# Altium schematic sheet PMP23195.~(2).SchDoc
size 431 x 279 mm; Date: Not shown in title block; ApprovedBy: Not shown in title block; CheckedBy: Not shown in title block; Author: Not shown in title block; CompanyName: Not shown in title block; Engineer: Not shown in title block; Organization: Not shown in title block; Address1: Not shown in title block; Address2: Not shown in title block; Address3: Not shown in title block; Address4: Not shown in title block; DocumentNumber: 1; Revision: Use project parameter SCH_Rev; SheetNumber: 1; SheetTotal: 2; PageSetup: Record=PageOptions¦CenterHorizontal=True¦CenterVertical=True¦PrintScale=1.00¦XCorrection=1.00¦YCorrection=1.00¦PrintKind=0¦BorderSize=5000000¦LeftOffset=0¦BottomOffset=0¦Orientation=2¦PaperLength=1000¦PaperWidth=1000¦Scale=100¦PaperSource=15¦PrintQuality=600¦MediaType=1¦DitherType=10¦PaperKind=Letter¦PrintScaleMode=1
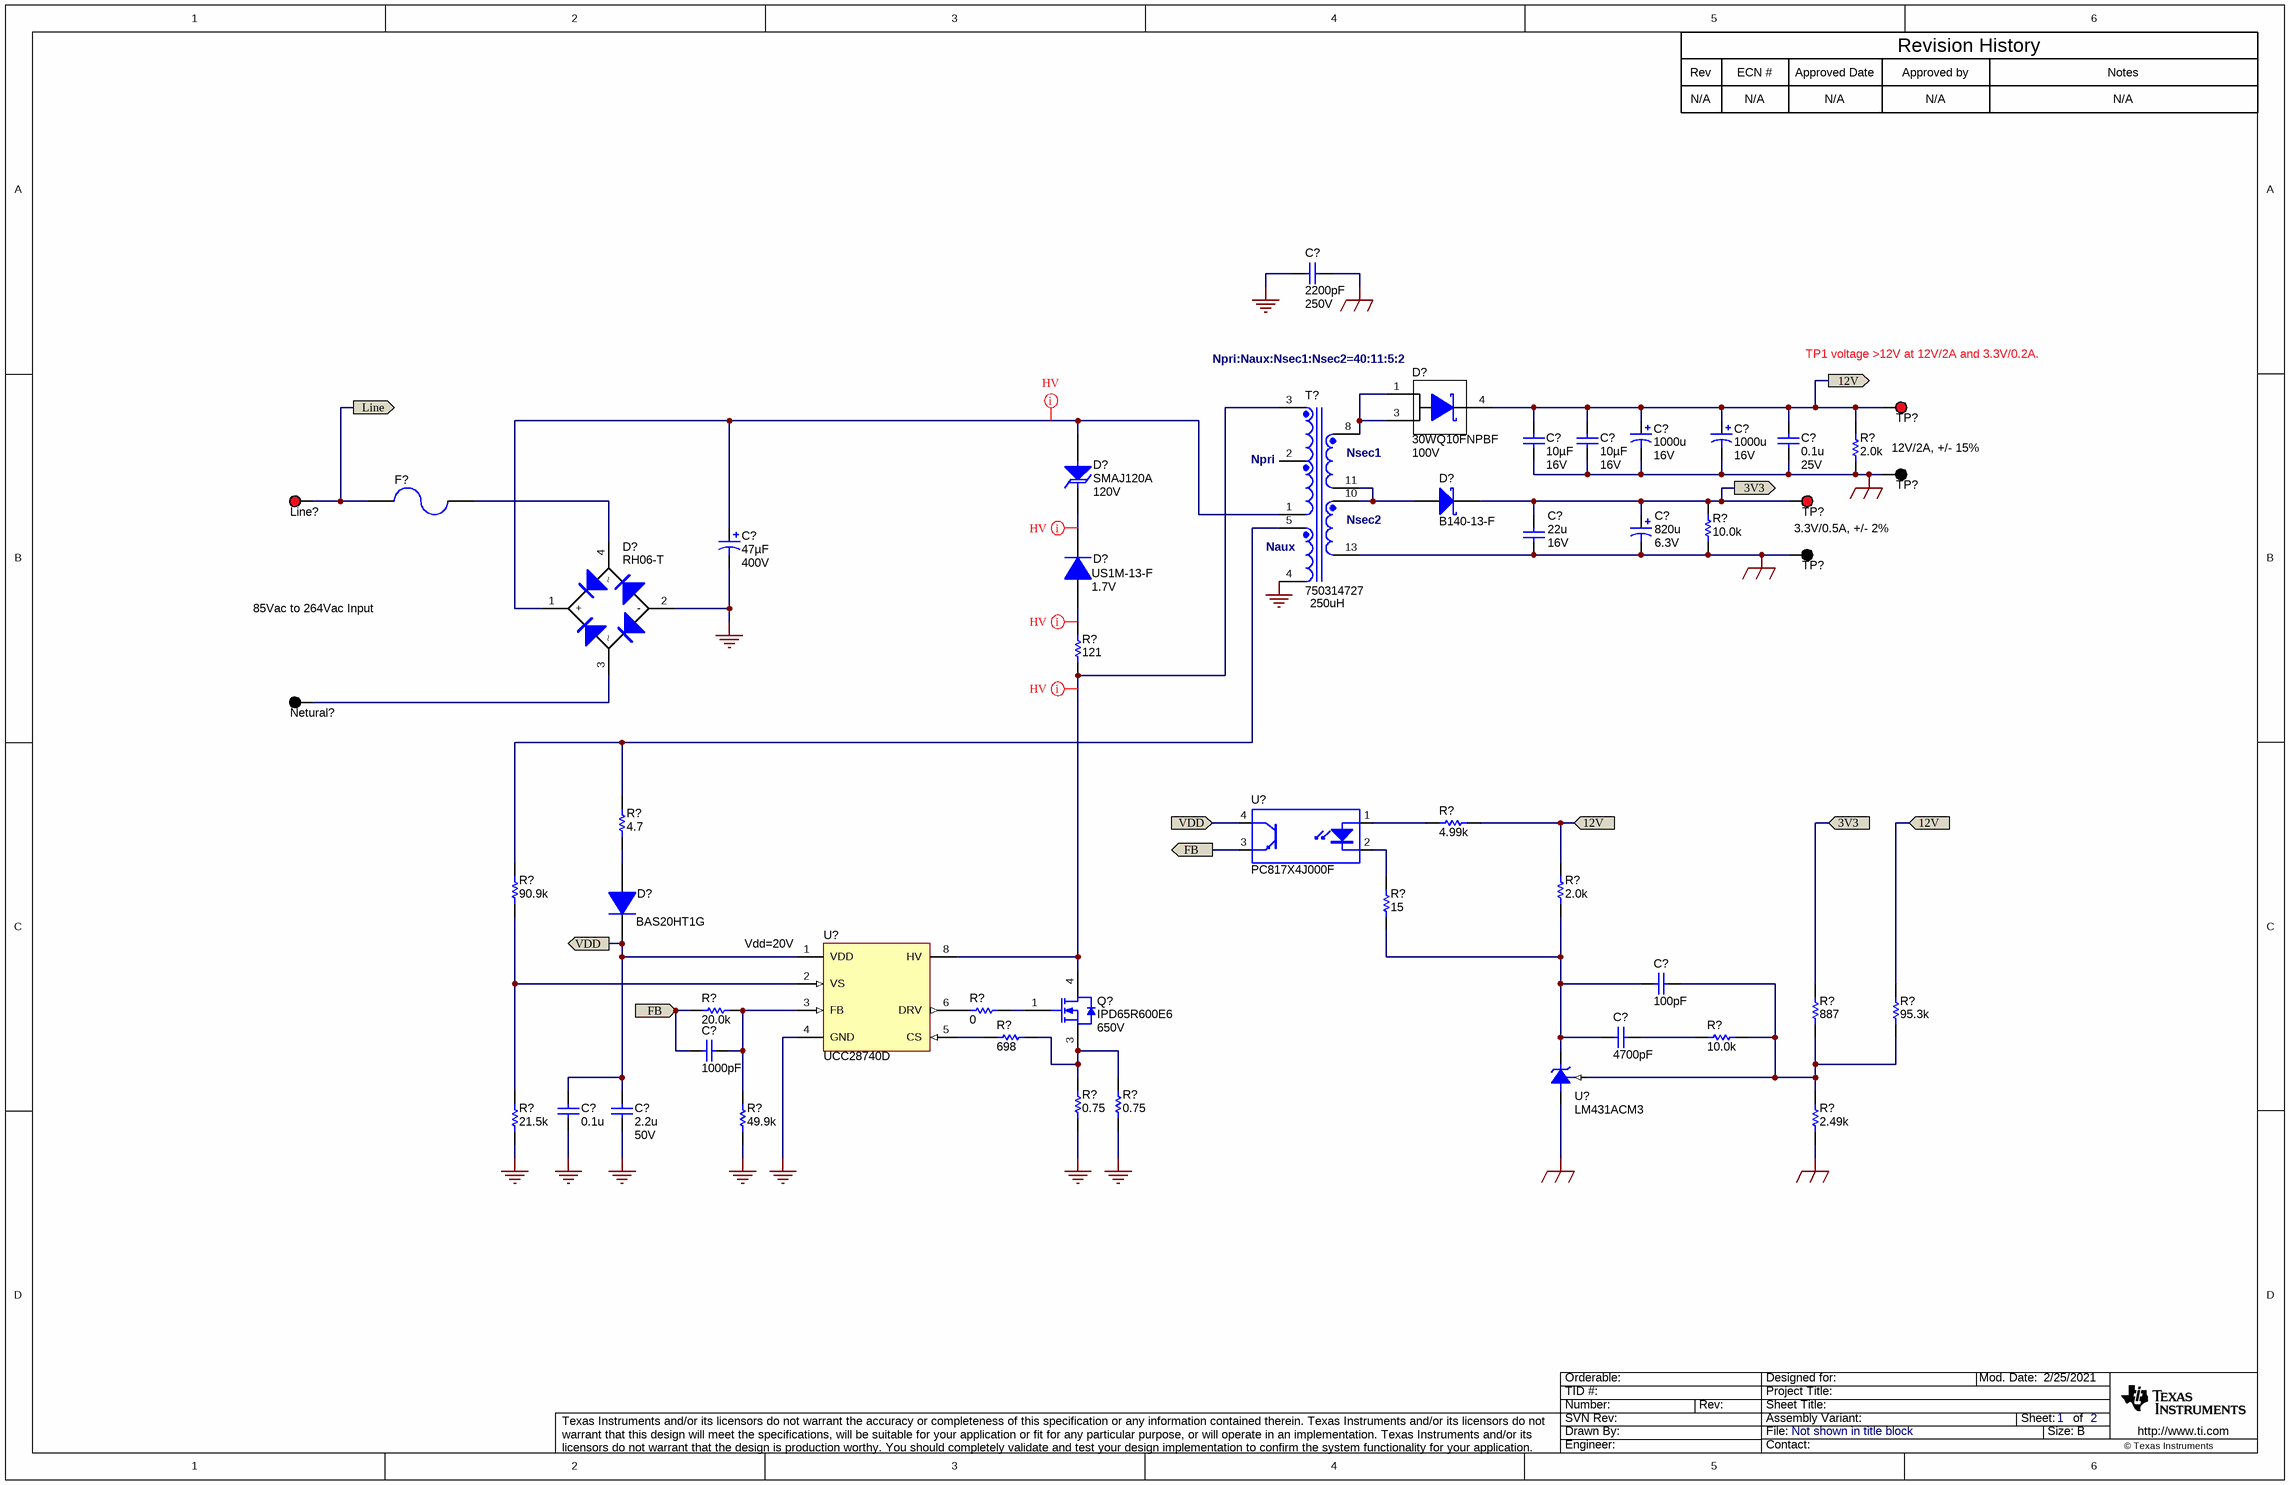
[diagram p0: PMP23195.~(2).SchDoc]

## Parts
(Parts that share a designator on the sheet are numbered #1, #2 ... from top to bottom, then left to right.)
C?#1  ValueDisplayed: 2200pF  Value2: 250V  [CAPRD750W60D1050H1450]  (hidden comment: CS11-E2GA222MYNS)
C?#2  ValueDisplayed: 10µF  Value2: 16V  [1206]  (hidden comment: C3216X5R1C106M)
C?#3  ValueDisplayed: 10µF  Value2: 16V  [1206]  (hidden comment: C3216X5R1C106M)
C?#4  ValueDisplayed: 1000u  Value2: 16V  [CAPPR5-10x16]  (hidden comment: 16YXJ1000MT810X16)
C?#5  ValueDisplayed: 1000u  Value2: 16V  [CAPPR5-10x16]  (hidden comment: 16YXJ1000MT810X16)
C?#6  ValueDisplayed: 0.1u  Value2: 25V  [0805_HV]  (hidden comment: 08053C104KAT2A)
C?#7  ValueDisplayed: 22u  Value2: 16V  [1206]  (hidden comment: 1206YD226MAT2A)
C?#8  ValueDisplayed: 820u  Value2: 6.3V  [CAPPR250W60D630H800]  (hidden comment: 6.3ZL820MEFC8x16)
C?#9  ValueDisplayed: 47µF  Value2: 400V  [CAPPR7.5-16X25]  (hidden comment: EEUED2G470)
C?#10  ValueDisplayed: 100pF  [0603]  (hidden comment: C1608C0G1H101J)
C?#11  ValueDisplayed: 4700pF  [0603]  (hidden comment: GRM188R71C472KA01D)
C?#12  ValueDisplayed: 1000pF  [0603]  (hidden comment: 06031C102MAT2A)
C?#13  ValueDisplayed: 0.1u  [0603]  (hidden comment: 06035C104KAT2A)
C?#14  ValueDisplayed: 2.2u  Value2: 50V  [1206]  (hidden comment: GRM31CR61H225KA88L)
D?#1  30WQ10FNPBF  value 100V  [DPAK]
D?#2  SMAJ120A  value 120V  [SMA]
D?#3  B140-13-F  [SMA]
D?#4  US1M-13-F  value 1.7V  [SMA]
D?#5  RH06-T  [MiniDIP]
D?#6  BAS20HT1G  [sod-323]
F?  FUSE FAST 250VAC 2A RADIAL  [FUSE_372]  (value not drawn)
Line?  5000  [Keystone5000]  (value not drawn)
Netural?  5001  [Keystone5001]  (value not drawn)
Q?  IPD65R600E6  value 650V  [DPAK]
R?#1  value 2.0k  [1206]  (hidden comment: CRCW12062K00JNEA)
R?#2  value 10.0k  [0603]  (hidden comment: CRCW060310K0FKEA)
R?#3  value 121  [1206]  (hidden comment: CRCW1206121RFKEA)
R?#4  value 4.7  [1206]  (hidden comment: CRCW12064R70JNEA)
R?#5  value 4.99k  [0805_HV]  (hidden comment: CRCW08054K99FKEA)
R?#6  value 90.9k  [0603]  (hidden comment: CRCW060390K9FKEA)
R?#7  value 2.0k  [1206]  (hidden comment: CRCW12062K00JNEA)
R?#8  value 15  [0603]  (hidden comment: CRCW060315R0JNEA)
R?#9  value 20.0k  [0603]  (hidden comment: CRCW060320K0FKEA)
R?#10  value 0  [0603]  (hidden comment: CRCW06030000Z0EA)
R?#11  value 887  [0603]  (hidden comment: CRCW0603887RFKEA)
R?#12  value 95.3k  [0603]  (hidden comment: CRCW060395K3FKEA)
R?#13  value 698  [0603]  (hidden comment: CRCW0603698RFKEA)
R?#14  value 10.0k  [0603]  (hidden comment: CRCW060310K0FKEA)
R?#15  value 0.75  [1206]  (hidden comment: CSR1206FKR750)
R?#16  value 0.75  [1206]  (hidden comment: CSR1206FKR750)
R?#17  value 21.5k  [1206]  (hidden comment: CRCW120621K5FKEA)
R?#18  value 49.9k  [0603]  (hidden comment: CRCW060349K9FKEA)
R?#19  value 2.49k  [0603]  (hidden comment: CRCW06032K49FKEA)
T?  750314727  value 250uH  [WURTH_750314727]
TP?#1  5000  [Keystone5000]  (value not drawn)
TP?#2  5001  [Keystone5001]  (value not drawn)
TP?#3  5000  [Keystone5000]  (value not drawn)
TP?#4  5001  [Keystone5001]  (value not drawn)
U?#1  PC817X4J000F  [DIP762W60P254L460H350Q4B]
U?#2  UCC28740D  [D0007A_N]
U?#3  LM431ACM3  [MF03A_N]

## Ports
3V3 (in), 3V3 (out), 12V (in), 12V (out), FB (in), FB (out), Line (out), VDD (in), VDD (out)

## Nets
GND: C?#1.2 C?#9.2(-) C?#13.2 C?#14.2 D?#5.2(-) R?#15.1 R?#16.1 R?#17.1 R?#18.1 T?.4 U?#2.4(GND)
GND2: C?#1.1 C?#2.2 C?#3.2 C?#4.2(-) C?#5.2(-) C?#6.2 C?#7.2 C?#8.2(-) R?#1.1 R?#2.1 R?#19.1 T?.13 TP?#2.1 TP?#4.1 U?#3.3(A)
3V3: C?#7.1 C?#8.1(+) D?#3.1(K) R?#2.2 R?#11.2 TP?#3.1 ; port 3V3
12V: C?#2.1 C?#3.1 C?#4.1(+) C?#5.1(+) C?#6.1 D?#1.4(K) R?#1.2 R?#5.2 R?#7.2 R?#12.2 TP?#1.1 ; port 12V
FB: C?#12.2 R?#9.1 U?#1.3(E) ; port FB
Line: F?.2 Line?.1 ; port Line
VDD: C?#13.1 C?#14.1 D?#6.1(K) U?#1.4(C) U?#2.1(VDD) ; port VDD
NetC?#9_1: C?#9.1(+) D?#2.2(A) D?#5.1(+) T?.1
NetC?#10_1: C?#10.1 R?#11.1 R?#12.1 R?#14.2 R?#19.2 U?#3.2(REF)
NetC?#10_2: C?#10.2 C?#11.2 R?#7.1 R?#8.2 U?#3.1(K)
NetC?#11_1: C?#11.1 R?#14.1
NetC?#12_1: C?#12.1 R?#9.2 R?#18.2 U?#2.3(FB)
NetD?#1_1: D?#1.1(A) D?#1.3(A) T?.8
NetD?#2_1: D?#2.1(K) D?#4.1(K)
NetD?#3_2: D?#3.2(A) T?.10 T?.11
NetD?#4_2: D?#4.2(A) R?#3.2
NetD?#5_3: D?#5.3 Netural?.1
NetD?#5_4: D?#5.4 F?.1
NetD?#6_2: D?#6.2(A) R?#4.1
NetQ?_1: Q?.1(G) R?#10.2
NetQ?_3: Q?.3(S) R?#13.2 R?#15.2 R?#16.2
NetQ?_4: Q?.4(D) R?#3.1 T?.3 U?#2.8(HV)
NetR?#4_2: R?#4.2 R?#6.2 T?.5
NetR?#5_1: R?#5.1 U?#1.1(A)
NetR?#6_1: R?#6.1 R?#17.2 U?#2.2(VS)
NetR?#8_1: R?#8.1 U?#1.2(K)
NetR?#10_1: R?#10.1 U?#2.6(DRV)
NetR?#13_1: R?#13.1 U?#2.5(CS)

Not connected (* = marked no-connect by the designer): T? 2

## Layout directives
net class HV: NetC?#9_1, NetD?#2_1, NetD?#4_2, NetQ?_4

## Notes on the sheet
- Rev
- N/A
- ECN #
- Approved Date
- Approved by
- Revision History
- Notes
- Npri:Naux:Nsec1:Nsec2=40:11:5:2
- TP1 voltage >12V at 12V/2A and 3.3V/0.2A.
- (near T?) Npri
- (near T?) Nsec1
- (near TP?#2) 12V/2A, +/- 15%
- (near T?) Naux
- (near T?) Nsec2
- (near TP?#4) 3.3V/0.5A, +/- 2%
- 85Vac to 264Vac Input
- (near U?#2) Vdd=20V

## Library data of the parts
C?#1 = CS11-E2GA222MYNS: CAP, CERM, 2200pF, 250V, +/-20%, E, Radial Disc D10.5x7mm; Manufacturer: TDK; Polarized: N; CompType: Capacitor; U/M: EA; Cap_F: 0.0000000022; Tolerance_%: 20; Value1: Unknown; VDC_V: 250; TaMin_C: -25; TaMax_C: 105; Cap_Case: Disc, 10.5x7mm
C?#2 C?#3 = C3216X5R1C106M: CAP, CERM, 10uF, 16V, +/-20%, X5R, 1206; Manufacturer: TDK; Polarized: N; CompType: Capacitor; U/M: EA; Cap_F: 0.00001; Tolerance_%: 20; ESR_Ohm: 0.0046; Value1: 0.0046 ohm; VDC_V: 16; IRMS_A: 2.7; TaMin_C: -55; TaMax_C: 85
C?#4 C?#5 = 16ZLJ1000MCE10X16: CAP ALUM 1000UF 16V 20% RADIAL; Manufacturer: Rubycon; Polarized: Y; CompType: Capacitor; U/M: EA; Cap_F: 0.001; Tolerance_%: 20; Value1: Unknown; VDC_V: 16; TaMin_C: -40; TaMax_C: 105; Cap_Case: 10x16
C?#6 = 08053C104KAT2A: CAP, CERM, 0.1uF, 25V, +/-10%, X7R, 0805; Manufacturer: AVX; Polarized: N; CompType: Capacitor; U/M: EA; Cap_F: 0.0000001; Tolerance_%: 10; ESR_Ohm: 0.28; Value1: 0.28 ohm; VDC_V: 25; TaMin_C: -55; TaMax_C: 125; Cap_Case: 0805
C?#7 = 1206YD226MAT2A: CAP, CERM, 22uF, 16V, +/-20%, X5R, 1206; Manufacturer: AVX; Polarized: N; CompType: Capacitor; U/M: EA; Cap_F: 0.000022; Tolerance_%: 20; Value1: Unknown; VDC_V: 16; TaMin_C: -55; TaMax_C: 85
C?#8 = RS80J471MDN1JT: CAP, AL, 820uF, 6.3V, +/-20%, 0.008 ohm, TH; Manufacturer: Rybycon; Polarized: Y; CompType: Capacitor; U/M: EA; Tolerance_%: 20; VDC_V: 6.3; ESR_Ohm: 0.008; IRMS_A: 5; TaMin_C: -55; TaMax_C: 105; Cap_Case: RCAP, 6.3x8
C?#9 = EEUED2G470: CAP, AL, 47uF, 400V, +/-20%, 0.609529 ohm, TH; Manufacturer: Panasonic; Polarized: Y; CompType: Capacitor; U/M: EA; Cap_F: 0.000047; Tolerance_%: 20; VDC_V: 400; IRMS_A: 0.84; TaMin_C: -25; TaMax_C: 105; AC_Derating: 0.3
C?#10 = C1608C0G1H101J: CAP, CERM, 100pF, 50V, +/-5%, C0G/NP0, 0603; Manufacturer: TDK; Polarized: N; CompType: Capacitor; U/M: EA; Cap_F: 0.0000000001; Tolerance_%: 5; ESR_Ohm: 0.1679; Value1: 0.1679 ohm; VDC_V: 50; TaMin_C: -55; TaMax_C: 125
C?#11 = GRM188R71C472KA01D: CAP, CERM, 4700pF, 16V, +/-10%, X7R, 0603; Manufacturer: MuRata; Polarized: N; CompType: Capacitor; U/M: EA; Cap_F: 0.0000000047; Tolerance_%: 10; Value1: Unknown; VDC_V: 16; TaMin_C: -55; TaMax_C: 125
C?#12 = 06031C102MAT2A: CAP, CERM, 1000pF, 100V, +/-20%, X7R, 0603; Manufacturer: AVX; Polarized: N; CompType: Capacitor; U/M: EA; Cap_F: 0.000000001; Tolerance_%: 20; ESR_Ohm: 0.276; Value1: 0.276 ohm; VDC_V: 100; TaMin_C: -55; TaMax_C: 125
C?#13 = 06035C104KAT2A: CAP, CERM, 0.1uF, 50V, +/-10%, X7R, 0603; Manufacturer: AVX; Polarized: N; CompType: Capacitor; U/M: EA; Cap_F: 0.0000001; Tolerance_%: 10; Value1: Unknown; VDC_V: 50; TaMin_C: -55; TaMax_C: 125
C?#14 = GRM31CR61H225KA88L: CAP, CERM, 2.2uF, 50V, +/-10%, X5R, 1206; Manufacturer: MuRata; Polarized: N; CompType: Capacitor; U/M: EA; Cap_F: 0.0000022; Tolerance_%: 10; Value1: Unknown; VDC_V: 50; TaMin_C: -55; TaMax_C: 85
D?#1 = 30WQ10FNPBF: Diode, Schottky, 100V, 3.5A, DPAK; Manufacturer: Vishay-Semiconductor; U/M: EA; Vf_V: 0.81; Value2: 0.81V; Io_A: 3.5; Vr_V: 100; TJmax_C: 150; RJC_CperW: 4.7
D?#2 = SMAJ120A: Diode, TVS, Uni, 120V, 400W, SMA; Manufacturer: Littelfuse; U/M: EA; Power_W: 400; Vr_V: 120
D?#3 = B140-13-F: Diode, Schottky, 40V, 1A, SMA; Manufacturer: Diodes Inc.; U/M: EA; Vf_V: 0.5; Value2: 0.5V; Io_A: 1; Vr_V: 40; TJmax_C: 150; RJC_CperW: 20
D?#4 = US1M-13-F: Diode, Ultrafast, 1000V, 1A, SMA; Manufacturer: Diodes Inc.; U/M: EA; Vf_V: 1.7; Io_A: 1; Vr_V: 1000; TJmax_C: 150; RJC_CperW: 30
D?#5 = RH06-T: Diode, Switching-Bridge, 600V, 0.5A, MiniDIP; Manufacturer: Diodes Inc.; Value: 1.15V; U/M: EA; Vf_V: 1.15; Io_A: 0.5; Vr_V: 600; TJmax_C: 150
D?#6 = BAS316,115: DIODE SWITCH 200V 200MA SOD323; U/M: EA; Vf_V: 1.4; Value1: 0.25A; Vr_V: 100; Value2: 100V; TJmax_C: 150; Type: Ultrafast
F? = 37215000001: PartNumber: 37012000410; Manufacturer: Littelfuse; U/M: EA; OpeningTime_100%_min: 4; OpeningTime_200%_max: 2; VDC_V: 250; MeltingTyp: 94; Vdrop: 0.08; Soldering_Wave_MaxTemp_C: 260; Soldering_Wave_MaxTime_s: 5
Line? TP?#1 TP?#3 = 5000: Test Point, TH, Miniature, Red; Manufacturer: Keystone; CompType: Test Point Loop; U/M: EA
Netural? TP?#2 TP?#4 = 5001: Test Point, TH, Miniature, Black; Manufacturer: Keystone; CompType: Test Point Loop; U/M: EA
Q? = AOD2N60: MOSFET N-CH 650V 7.3A TO252; Manufacturer: Infineon; Alternate Manufacturer: None; U/M: EA; ChType: N; VdsMax_V: 650; Value1: ? ohm; Value2: 9.5 nC; QgTyp_nC: 9.5; Vgs_V: 30; IdsMax_A: 2
R?#1 R?#7 = CRCW12062K00JNEA: RES, 2.0k ohm, 5%, 0.25W, 1206; Manufacturer: Vishay-Dale; CompType: Resistor; Res_ohm: 2000; Value_Code: 2k00; Tolerance_%: 5; Power_W: 0.25; VDC_V: 200; TempCo: 200 ppm/C; EIA_Code: E24; U/M: EA
R?#2 R?#14 = CRCW060310K0FKEA: RES, 10.0k ohm, 1%, 0.1W, 0603; Manufacturer: Vishay-Dale; CompType: Resistor; Res_ohm: 10000; Value_Code: 10k0; Tolerance_%: 1; Power_W: 0.1; VDC_V: 75; TempCo: 100 ppm/C; EIA_Code: E96; U/M: EA
R?#3 = CRCW1206121RFKEA: RES, 121 ohm, 1%, 0.25W, 1206; Manufacturer: Vishay-Dale; CompType: Resistor; Value_Code: 121R; Tolerance_%: 1; Power_W: 0.25; VDC_V: 200; TempCo: 100 ppm/C; EIA_Code: E96; U/M: EA
R?#4 = CRCW12064R70JNEA: RES, 4.7 ohm, 5%, 0.25W, 1206; Manufacturer: Vishay-Dale; CompType: Resistor; Value_Code: 4R70; Tolerance_%: 5; Power_W: 0.25; VDC_V: 200; TempCo: 200 ppm/C; EIA_Code: E24; U/M: EA
R?#5 = CRCW08054K99FKEA: RES, 4.99k ohm, 1%, 0.125W, 0805; Manufacturer: Vishay-Dale; CompType: Resistor; Res_ohm: 4990; Value_Code: 4k99; Tolerance_%: 1; Power_W: 0.125; VDC_V: 150; TempCo: 100 ppm/C; EIA_Code: E96; U/M: EA
R?#6 = CRCW060390K9FKEA: RES, 90.9k ohm, 1%, 0.1W, 0603; Manufacturer: Vishay-Dale; CompType: Resistor; Res_ohm: 90900; Value_Code: 90k9; Tolerance_%: 1; Power_W: 0.1; VDC_V: 75; TempCo: 100 ppm/C; EIA_Code: E96; U/M: EA
R?#8 = CRCW060315R0JNEA: RES, 15 ohm, 5%, 0.1W, 0603; Manufacturer: Vishay-Dale; CompType: Resistor; Value_Code: 15R0; Tolerance_%: 5; Power_W: 0.1; VDC_V: 75; TempCo: 200 ppm/C; EIA_Code: E24; U/M: EA
R?#9 = CRCW060320K0FKEA: RES, 20.0k ohm, 1%, 0.1W, 0603; Manufacturer: Vishay-Dale; CompType: Resistor; Res_ohm: 20000; Value_Code: 20k0; Tolerance_%: 1; Power_W: 0.1; VDC_V: 75; TempCo: 100 ppm/C; EIA_Code: E96; U/M: EA
R?#10 = CRCW06030000Z0EA: RES, 0 ohm, 5%, 0.1W, 0603; Manufacturer: Vishay-Dale; CompType: Resistor; Value_Code: 0000; Tolerance_%: 5; Power_W: 0.1; VDC_V: 75; TempCo: 200 ppm/C; EIA_Code: E24; U/M: EA
R?#11 = CRCW0603887RFKEA: RES, 887 ohm, 1%, 0.1W, 0603; Manufacturer: Vishay-Dale; CompType: Resistor; Value_Code: 887R; Tolerance_%: 1; Power_W: 0.1; VDC_V: 75; TempCo: 100 ppm/C; EIA_Code: E96; U/M: EA
R?#12 = CRCW060395K3FKEA: RES, 95.3k ohm, 1%, 0.1W, 0603; Manufacturer: Vishay-Dale; CompType: Resistor; Res_ohm: 95300; Value_Code: 95k3; Tolerance_%: 1; Power_W: 0.1; VDC_V: 75; TempCo: 100 ppm/C; EIA_Code: E96; U/M: EA
R?#13 = CRCW0603698RFKEA: RES, 698 ohm, 1%, 0.1W, 0603; Manufacturer: Vishay-Dale; CompType: Resistor; Value_Code: 698R; Tolerance_%: 1; Power_W: 0.1; VDC_V: 75; TempCo: 100 ppm/C; EIA_Code: E96; U/M: EA
R?#15 R?#16 = CSR1206FKR750: RES, 0.75 ohm, 1%, 0.5W, 1206; Manufacturer: Stackpole Electronics Inc; CompType: Resistor; Value_Code: R750; Tolerance_%: 1; Power_W: 0.5; TempCo: 100 ppm/C; EIA_Code: E96; U/M: EA
R?#17 = CRCW120621K5FKEA: RES, 21.5k ohm, 1%, 0.25W, 1206; Manufacturer: Vishay-Dale; CompType: Resistor; Res_ohm: 21500; Value_Code: 21k5; Tolerance_%: 1; Power_W: 0.25; VDC_V: 200; TempCo: 100 ppm/C; EIA_Code: E96; U/M: EA
R?#18 = CRCW060349K9FKEA: RES, 49.9k ohm, 1%, 0.1W, 0603; Manufacturer: Vishay-Dale; CompType: Resistor; Res_ohm: 49900; Value_Code: 49k9; Tolerance_%: 1; Power_W: 0.1; VDC_V: 75; TempCo: 100 ppm/C; EIA_Code: E96; U/M: EA
R?#19 = CRCW06032K49FKEA: RES, 2.49k ohm, 1%, 0.1W, 0603; Manufacturer: Vishay-Dale; CompType: Resistor; Res_ohm: 2490; Value_Code: 2k49; Tolerance_%: 1; Power_W: 0.1; VDC_V: 75; TempCo: 100 ppm/C; EIA_Code: E96; U/M: EA
T? = 750314727: Transformer, 80uH, TH; Manufacturer: Wurth Elektronik eiSos; SymbolCreator: x0208325; DCR_Ohm: 0.221; LeakageL: TBD; U/M: EA
U?#1 = LTV-817: Opto-Isolator, 1 Channel, TH; CompType: OPTOCOUPLER; U/M: EA
U?#2 = UCC28740D: Constant-Voltage, Constant-Current Flyback Controller Using Opto-Coupler Feedback, D0007A; Alternate Manufacturer: None; Manufacturer: Texas Instruments; SymbolCreator: a0412235; CompType: IC; U/M: EA
U?#3 = LM431ACM3: Adjustable Precision Zener Shunt Regulator, 3-pin SOT-23; Manufacturer: National Semiconductor; PackageTopMarking: N1F*XTT; PowerWise: N; CompType: MiscPower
